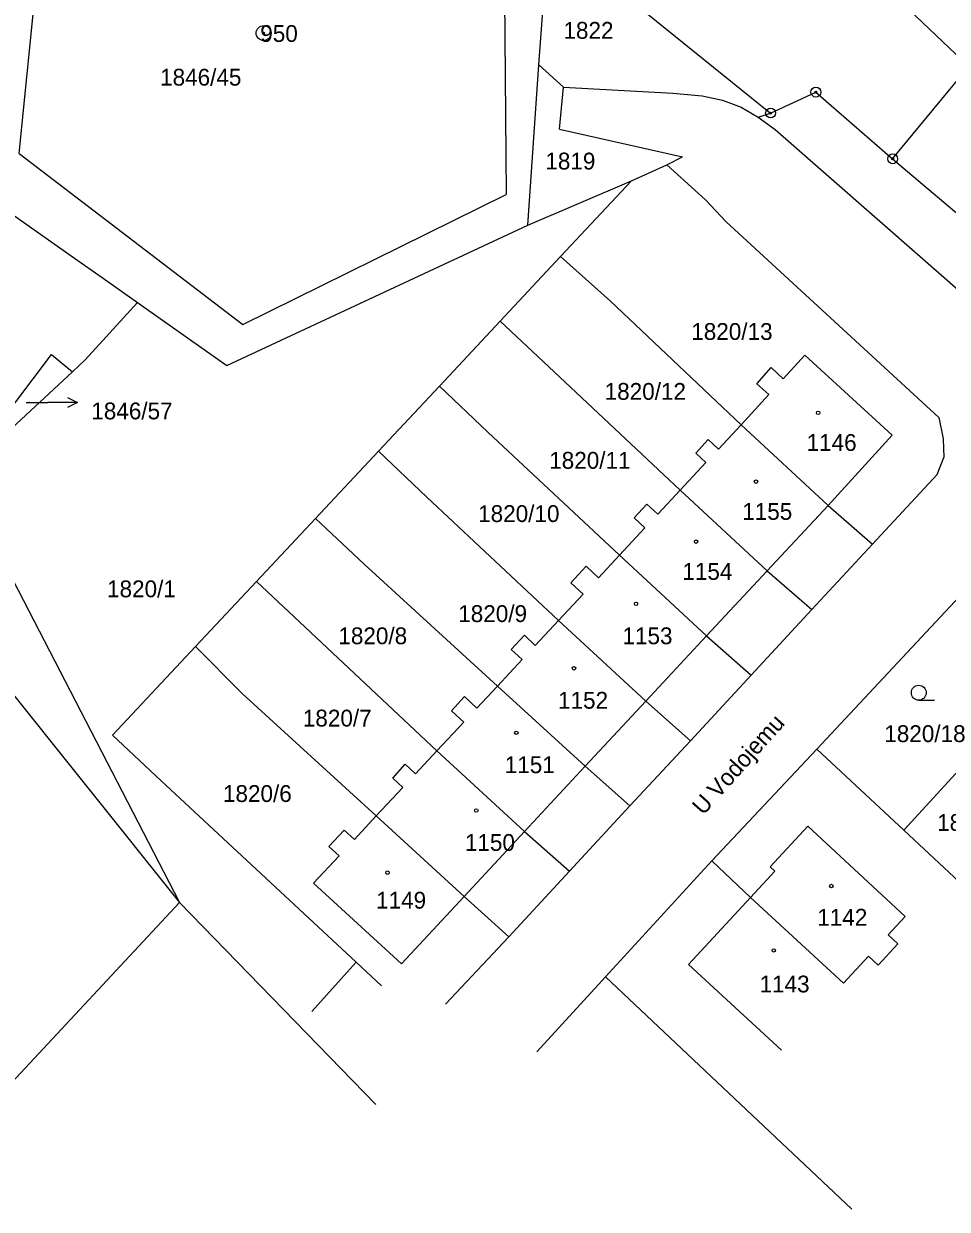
# Model space of a CAD drawing. Extents: x -763205 to -760228, y -1155311 to -1152844.
# Drawn here: x -761916.2 to -761822.9, y -1155174.3 to -1155054.6 of the extents above; entities that cross this region are included whole.
import ezdxf

# ---------------------------------------------------------------- set-up
doc = ezdxf.new("R2010")
doc.units = 0
for name, color, linetype in [('Vrstva 1', 7, 'Continuous'), ('Vrstva 15', 7, 'Continuous'), ('Vrstva 16', 7, 'Continuous'), ('Vrstva 17', 7, 'Continuous'), ('Vrstva 18', 7, 'Continuous'), ('Vrstva 19', 7, 'Continuous'), ('Vrstva 24', 7, 'Continuous'), ('Vrstva 25', 7, 'Continuous'), ('Vrstva 4', 7, 'Continuous'), ('Vrstva 6', 7, 'Continuous')]:
    doc.layers.add(name, color=color, linetype=linetype)

msp = doc.modelspace()

# ---------------------------------------------------------------- linework, layer by layer
at = {"layer": 'Vrstva 1'}
for p, q in [((-761916.7, -1155067.65), (-761914, -1155041.09)), ((-761838.78, -1155041.7), (-761820.77, -1155058.87)), ((-761867.73, -1155043.2), (-761867.5, -1155071.79)), ((-761864.18, -1155058.7), (-761863.25, -1155045.45)), ((-761863.25, -1155045.45), (-761840.78, -1155063.58)), ((-761865.32, -1155074.89), (-761864.18, -1155058.7)), ((-761828.45, -1155068.2), (-761820.77, -1155058.87)), ((-761862.1, -1155065.21), (-761861.69, -1155060.97)), ((-761861.69, -1155060.97), (-761850.66, -1155061.58)), ((-761850.66, -1155061.58), (-761847.69, -1155061.84)), ((-761847.69, -1155061.84), (-761845.64, -1155062.29)), ((-761840.78, -1155063.58), (-761836.21, -1155061.47)), ((-761836.21, -1155061.47), (-761828.45, -1155068.2)), ((-761845.64, -1155062.29), (-761843.77, -1155062.98)), ((-761843.77, -1155062.98), (-761842.05, -1155064.01)), ((-761842.05, -1155064.01), (-761840.78, -1155063.58)), ((-761842.05, -1155064.01), (-761840.31, -1155065.25)), ((-761862.1, -1155065.21), (-761849.69, -1155068)), ((-761840.31, -1155065.25), (-761769.79, -1155127.04)), ((-761916.7, -1155067.65), (-761894.1, -1155084.93)), ((-761854.82, -1155070.43), (-761851.26, -1155068.82)), ((-761851.26, -1155068.82), (-761849.69, -1155068)), ((-761851.26, -1155068.82), (-761847.37, -1155072.36)), ((-761828.45, -1155068.2), (-761805.45, -1155087.73)), ((-761923.1, -1155069.78), (-761911.09, -1155078.25)), ((-761865.32, -1155074.89), (-761854.82, -1155070.43)), ((-761861.99, -1155078.08), (-761854.82, -1155070.43)), ((-761894.1, -1155084.93), (-761867.5, -1155071.79)), ((-761847.37, -1155072.36), (-761845.26, -1155074.55)), ((-761895.71, -1155089.09), (-761865.32, -1155074.89)), ((-761845.26, -1155074.55), (-761823.79, -1155094.31)), ((-761911.09, -1155078.25), (-761908.32, -1155080.2)), ((-761868.09, -1155084.59), (-761861.99, -1155078.08)), ((-761861.99, -1155078.08), (-761856.96, -1155082.59)), ((-761908.32, -1155080.2), (-761904.75, -1155082.72)), ((-761910.02, -1155088.49), (-761904.75, -1155082.72)), ((-761904.75, -1155082.72), (-761895.71, -1155089.09)), ((-761856.96, -1155082.59), (-761843.76, -1155095.06)), ((-761874.24, -1155091.16), (-761868.09, -1155084.59)), ((-761868.09, -1155084.59), (-761863.17, -1155089.22)), ((-761839.5, -1155090.41), (-761837.32, -1155088.03)), ((-761837.32, -1155088.03), (-761828.51, -1155096.1)), ((-761911.32, -1155089.7), (-761910.02, -1155088.49)), ((-761863.17, -1155089.22), (-761849.91, -1155101.66)), ((-761842.18, -1155090.91), (-761840.71, -1155089.29)), ((-761840.71, -1155089.29), (-761839.5, -1155090.41)), ((-761922.74, -1155100.28), (-761911.32, -1155089.7)), ((-761880.38, -1155097.71), (-761874.24, -1155091.16)), ((-761874.24, -1155091.16), (-761869.34, -1155095.8)), ((-761842.18, -1155090.91), (-761840.97, -1155092.01)), ((-761843.76, -1155095.06), (-761840.97, -1155092.01)), ((-761846.05, -1155097.52), (-761843.76, -1155095.06)), ((-761843.76, -1155095.06), (-761834.98, -1155103.2)), ((-761823.79, -1155094.31), (-761823.36, -1155096.48)), ((-761869.34, -1155095.8), (-761856.04, -1155108.22)), ((-761848.35, -1155097.93), (-761847.08, -1155096.56)), ((-761847.08, -1155096.56), (-761846.05, -1155097.52)), ((-761834.98, -1155103.2), (-761828.51, -1155096.1)), ((-761823.36, -1155096.48), (-761823.28, -1155098.35)), ((-761886.77, -1155104.53), (-761880.38, -1155097.71)), ((-761880.38, -1155097.71), (-761875.5, -1155102.37)), ((-761849.91, -1155101.66), (-761847.32, -1155098.88)), ((-761848.35, -1155097.93), (-761847.32, -1155098.88)), ((-761823.95, -1155100.07), (-761823.28, -1155098.35)), ((-761922.74, -1155100.28), (-761900.49, -1155143.31)), ((-761830.47, -1155107.1), (-761823.95, -1155100.07)), ((-761875.5, -1155102.37), (-761862.21, -1155114.84)), ((-761852.18, -1155104.09), (-761849.91, -1155101.66)), ((-761849.91, -1155101.66), (-761841.12, -1155109.8)), ((-761854.58, -1155104.45), (-761853.28, -1155103.06)), ((-761853.28, -1155103.06), (-761852.18, -1155104.09)), ((-761834.98, -1155103.2), (-761830.47, -1155107.1)), ((-761892.72, -1155110.88), (-761886.77, -1155104.53)), ((-761886.77, -1155104.53), (-761881.83, -1155109.12)), ((-761854.58, -1155104.45), (-761853.48, -1155105.48)), ((-761856.04, -1155108.22), (-761853.48, -1155105.48)), ((-761836.61, -1155113.72), (-761830.47, -1155107.1)), ((-761858.18, -1155110.51), (-761856.04, -1155108.22)), ((-761856.04, -1155108.22), (-761847.24, -1155116.37)), ((-761881.83, -1155109.12), (-761868.37, -1155121.44)), ((-761860.95, -1155111.02), (-761859.42, -1155109.35)), ((-761859.42, -1155109.35), (-761858.18, -1155110.51)), ((-761841.12, -1155109.8), (-761836.61, -1155113.72)), ((-761836.11, -1155127.83), (-761819.17, -1155109.69)), ((-761898.87, -1155117.45), (-761892.72, -1155110.88)), ((-761892.72, -1155110.88), (-761887.8, -1155115.48)), ((-761860.95, -1155111.02), (-761859.72, -1155112.17)), ((-761862.21, -1155114.84), (-761859.72, -1155112.17)), ((-761842.75, -1155120.34), (-761836.61, -1155113.72)), ((-761887.8, -1155115.48), (-761874.5, -1155128)), ((-761864.55, -1155117.34), (-761862.21, -1155114.84)), ((-761862.21, -1155114.84), (-761853.37, -1155122.96)), ((-761866.98, -1155117.75), (-761865.65, -1155116.32)), ((-761865.65, -1155116.32), (-761864.55, -1155117.34)), ((-761847.24, -1155116.37), (-761842.75, -1155120.34)), ((-761907.27, -1155126.41), (-761898.87, -1155117.45)), ((-761898.87, -1155117.45), (-761894.13, -1155122.24)), ((-761866.98, -1155117.75), (-761865.88, -1155118.77)), ((-761868.37, -1155121.44), (-761865.88, -1155118.77)), ((-761848.88, -1155126.96), (-761842.75, -1155120.34)), ((-761870.46, -1155123.68), (-761868.37, -1155121.44)), ((-761868.37, -1155121.44), (-761859.5, -1155129.54)), ((-761894.13, -1155122.24), (-761880.62, -1155134.56)), ((-761873.01, -1155123.95), (-761871.7, -1155122.51)), ((-761871.7, -1155122.51), (-761870.46, -1155123.68)), ((-761853.37, -1155122.96), (-761848.88, -1155126.96)), ((-761873.01, -1155123.95), (-761871.78, -1155125.1)), ((-761827.32, -1155136.01), (-761816.36, -1155124.02)), ((-761874.5, -1155128), (-761871.78, -1155125.1)), ((-761907.27, -1155126.41), (-761902.34, -1155131)), ((-761855, -1155133.55), (-761848.88, -1155126.96)), ((-761876.65, -1155130.32), (-761874.5, -1155128)), ((-761874.5, -1155128), (-761865.63, -1155136.13)), ((-761846.71, -1155139.09), (-761836.11, -1155127.83)), ((-761836.11, -1155127.83), (-761827.32, -1155136.01)), ((-761878.96, -1155130.73), (-761877.71, -1155129.33)), ((-761877.71, -1155129.33), (-761876.65, -1155130.32)), ((-761859.5, -1155129.54), (-761855, -1155133.55)), ((-761902.34, -1155131), (-761882.64, -1155149.32)), ((-761878.96, -1155130.73), (-761877.93, -1155131.69)), ((-761880.62, -1155134.56), (-761877.93, -1155131.69)), ((-761861.1, -1155140.13), (-761855, -1155133.55)), ((-761882.83, -1155136.94), (-761880.62, -1155134.56)), ((-761880.62, -1155134.56), (-761871.75, -1155142.71)), ((-761885.41, -1155137.63), (-761883.87, -1155135.98)), ((-761883.87, -1155135.98), (-761882.83, -1155136.94)), ((-761865.63, -1155136.13), (-761861.1, -1155140.13)), ((-761840.83, -1155139.71), (-761837.01, -1155135.59)), ((-761837.01, -1155135.59), (-761827.18, -1155144.71)), ((-761827.32, -1155136.01), (-761820.73, -1155142.14)), ((-761885.41, -1155137.63), (-761884.38, -1155138.6)), ((-761886.95, -1155141.36), (-761884.38, -1155138.6)), ((-761857.45, -1155150.79), (-761846.71, -1155139.09)), ((-761846.71, -1155139.09), (-761842.82, -1155142.78)), ((-761840.83, -1155139.71), (-761840.36, -1155140.14)), ((-761867.24, -1155146.76), (-761861.1, -1155140.13)), ((-761842.82, -1155142.78), (-761840.36, -1155140.14)), ((-761886.95, -1155141.36), (-761878.07, -1155149.5)), ((-761918.39, -1155162.48), (-761900.49, -1155143.31)), ((-761900.49, -1155143.31), (-761880.66, -1155163.71)), ((-761878.07, -1155149.5), (-761871.75, -1155142.71)), ((-761871.75, -1155142.71), (-761867.24, -1155146.76)), ((-761849.09, -1155149.55), (-761842.82, -1155142.78)), ((-761842.82, -1155142.78), (-761833.43, -1155151.45)), ((-761828.91, -1155146.58), (-761827.18, -1155144.71)), ((-761873.62, -1155153.58), (-761867.24, -1155146.76)), ((-761828.91, -1155146.58), (-761827.94, -1155147.48)), ((-761829.93, -1155149.62), (-761827.94, -1155147.48)), ((-761884.17, -1155151.02), (-761882.64, -1155149.32)), ((-761882.64, -1155149.32), (-761880.09, -1155151.7)), ((-761833.43, -1155151.45), (-761830.89, -1155148.72)), ((-761830.89, -1155148.72), (-761829.93, -1155149.62)), ((-761849.09, -1155149.55), (-761839.69, -1155158.2)), ((-761887.12, -1155154.3), (-761884.17, -1155151.02)), ((-761864.4, -1155158.39), (-761857.45, -1155150.79)), ((-761857.45, -1155150.79), (-761832.56, -1155174.28))]:
    msp.add_line(p, q, dxfattribs=at)
at = {"layer": 'Vrstva 16'}
for p in [(-761916, -1155092.81), (-761910.8, -1155092.811)]:
    msp.add_line(p, (-761913.8, -1155092.81), dxfattribs=at)
msp.add_lwpolyline([(-761911.8, -1155092.311), (-761910.8, -1155092.811), (-761911.8, -1155093.311)], dxfattribs=at)
at = {"layer": 'Vrstva 24'}
for centre, radius in [((-761892, -1155055.51), 0.75), ((-761892, -1155055.51), 0.1), ((-761836.21, -1155061.47), 0.5), ((-761836.21, -1155061.47), 0.1), ((-761840.78, -1155063.58), 0.5), ((-761840.78, -1155063.58), 0.1), ((-761828.45, -1155068.2), 0.5), ((-761828.45, -1155068.2), 0.1)]:
    msp.add_circle(centre, radius, dxfattribs=at)
at = {"layer": 'Vrstva 25'}
msp.add_line((-761825.81, -1155122.87), (-761824.21, -1155122.87), dxfattribs=at)
for centre, radius in [((-761835.98, -1155093.85), 0.175), ((-761842.26, -1155100.8), 0.175), ((-761848.31, -1155106.86), 0.175), ((-761854.37, -1155113.14), 0.175), ((-761860.64, -1155119.65), 0.175), ((-761825.81, -1155122.12), 0.75), ((-761866.47, -1155126.16), 0.175), ((-761870.51, -1155134.01), 0.175), ((-761879.48, -1155140.29), 0.175), ((-761834.64, -1155141.64), 0.175), ((-761840.46, -1155148.14), 0.175)]:
    msp.add_circle(centre, radius, dxfattribs=at)
at = {"layer": 'Vrstva 4'}
for p, q in [((-761841.12, -1155109.8), (-761834.98, -1155103.2)), ((-761847.24, -1155116.37), (-761841.12, -1155109.8)), ((-761853.37, -1155122.96), (-761847.24, -1155116.37)), ((-761859.5, -1155129.54), (-761853.37, -1155122.96)), ((-761865.63, -1155136.13), (-761859.5, -1155129.54)), ((-761871.75, -1155142.71), (-761865.63, -1155136.13))]:
    msp.add_line(p, q, dxfattribs=at)
at = {"layer": 'Vrstva 6'}
for p, q in [((-761864.18, -1155058.7), (-761861.69, -1155060.97)), ((-761922.74, -1155100.28), (-761913.41, -1155087.96)), ((-761913.41, -1155087.96), (-761911.32, -1155089.7)), ((-761927.37, -1155109.75), (-761900.49, -1155143.31))]:
    msp.add_line(p, q, dxfattribs=at)

# ---------------------------------------------------------------- texts
at = {"layer": 'Vrstva 15'}
msp.add_text('U Vodojemu', height=1.7, rotation=48.12846, dxfattribs=at).set_placement((-761847.592, -1155134.564))
at = {"layer": 'Vrstva 16'}
msp.add_text('1846/57', height=1.7, dxfattribs=at).set_placement((-761909.407, -1155094.51))
at = {"layer": 'Vrstva 17'}
msp.add_text('950', height=1.7, dxfattribs=at).set_placement((-761892.338, -1155056.4))
at = {"layer": 'Vrstva 18'}
for s, height, p in [('1822', 1.7, (-761861.707, -1155056.08)), ('1846/45', 1.7, (-761902.457, -1155060.81)), ('1819', 1.7, (-761863.537, -1155069.28)), ('1820/13', 1.7, (-761848.797, -1155086.49)), ('1820/12', 1.7, (-761857.547, -1155092.54)), ('1846/57', 0.1, (-761915.977, -1155092.81)), ('1820/11', 1.7, (-761863.147, -1155099.5)), ('1820/10', 1.7, (-761870.327, -1155104.88)), ('1820/1', 1.7, (-761907.817, -1155112.48)), ('1820/9', 1.7, (-761872.337, -1155114.98)), ('1820/8', 1.7, (-761884.447, -1155117.22)), ('1820/7', 1.7, (-761888.037, -1155125.53)), ('1820/18', 1.7, (-761829.297, -1155127.1)), ('1820/6', 1.7, (-761896.107, -1155133.15)), ('1820/19', 1.7, (-761823.957, -1155136.07))]:
    msp.add_text(s, height=height, dxfattribs=at).set_placement(p)
at = {"layer": 'Vrstva 19'}
for s, p in [('1146', (-761837.147, -1155097.7)), ('1155', (-761843.647, -1155104.66)), ('1154', (-761849.697, -1155110.72)), ('1153', (-761855.747, -1155117.22)), ('1152', (-761862.257, -1155123.73)), ('1151', (-761867.637, -1155130.24)), ('1150', (-761871.667, -1155138.09)), ('1149', (-761880.637, -1155143.92)), ('1142', (-761836.067, -1155145.64)), ('1143', (-761841.897, -1155152.38))]:
    msp.add_text(s, height=1.7, dxfattribs=at).set_placement(p)

doc.saveas('drawing.dxf')
